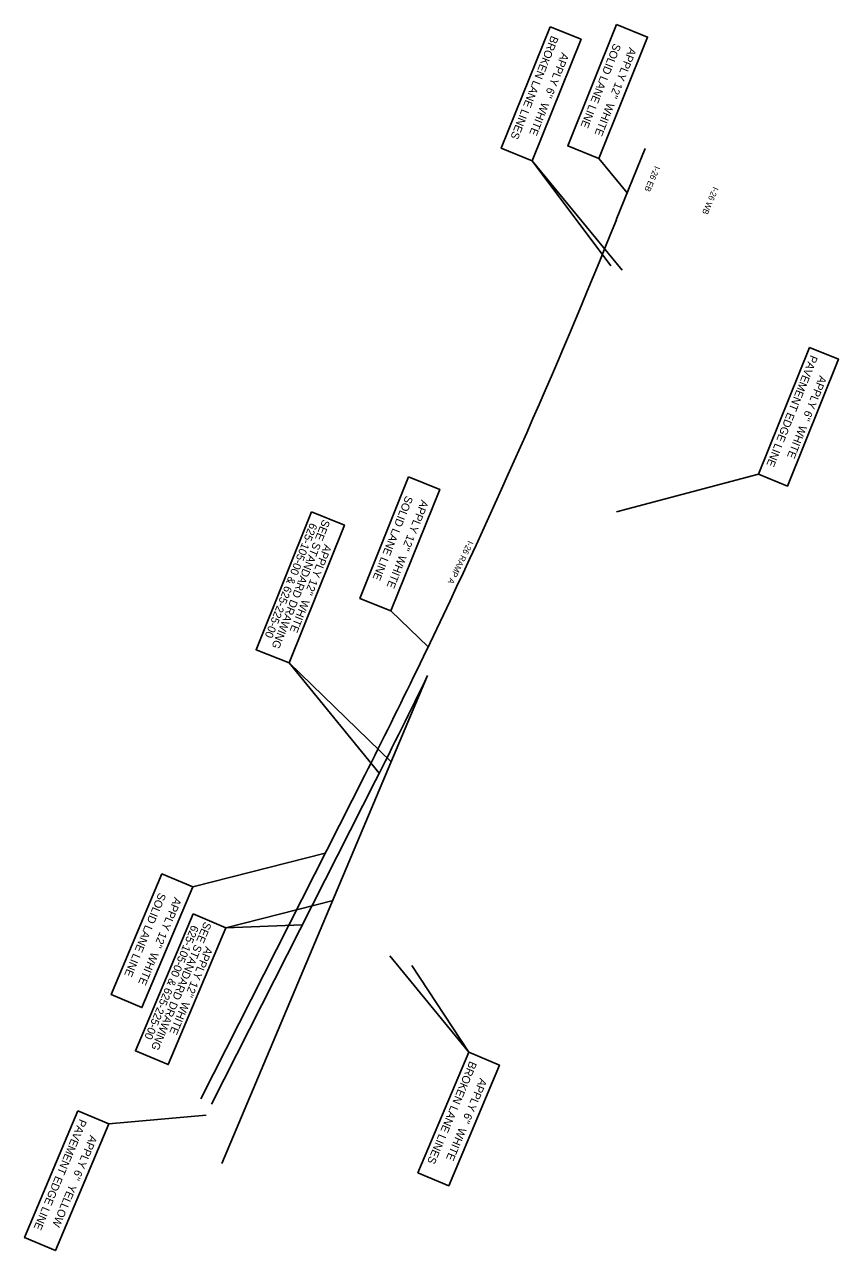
# Model space of a CAD drawing. Extents: x 1966013 to 1974896, y 789499 to 804826.
# Drawn here: x 1966799 to 1967612, y 793004 to 794229 of the extents above; entities that cross this region are included whole.
import ezdxf

# ---------------------------------------------------------------- set-up
doc = ezdxf.new("R2010")
doc.units = 0
for name, color, linetype in [('RD_EX_H2O_BlueLn', 7, 'Continuous'), ('RD_PD_Final_LnLine', 7, 'Continuous'), ('RD_PD_MedBWall', 7, 'Continuous')]:
    doc.layers.add(name, color=color, linetype=linetype)

msp = doc.modelspace()

# ---------------------------------------------------------------- linework, layer by layer
at = {"layer": 'RD_EX_H2O_BlueLn'}
for p, q in [((1967306.2, 794093.2), (1967396, 793983.7)), ((1967306.2, 794093.2), (1967384.8, 793988.1)), ((1967372.6, 794095.5), (1967401, 794060.9)), ((1967390.3, 793742.2), (1967532.4, 793779.7)), ((1967164.8, 793643.2), (1967202, 793607.2)), ((1967063, 793591.2), (1967153.2, 793481.1)), ((1967063, 793591.2), (1967165.2, 793492.3)), ((1966966.8, 793367.2), (1967099.1, 793401)), ((1966999.9, 793326.5), (1967107, 793353.8)), ((1966999.9, 793326.5), (1967076.2, 793329.5)), ((1967163.7, 793298.4), (1967242.6, 793202)), ((1967185.6, 793288.6), (1967242.6, 793202)), ((1966882.8, 793130.4), (1966980.1, 793139))]:
    msp.add_line(p, q, dxfattribs=at)
for points in [[(1967323.9, 794227.1), (1967275.2, 794105.7), (1967306.2, 794093.2), (1967355, 794214.6)], [(1967390.4, 794229.3), (1967341.6, 794107.9), (1967372.6, 794095.5), (1967421.4, 794216.8)], [(1967583.4, 793906.5), (1967532.4, 793779.7), (1967561.3, 793768), (1967612.3, 793894.9)], [(1967182.5, 793777.1), (1967133.8, 793655.7), (1967164.8, 793643.2), (1967213.6, 793764.6)], [(1967085.4, 793742.3), (1967030, 793604.4), (1967063, 793591.2), (1967118.4, 793729)], [(1966936, 793380.2), (1966885.2, 793259.6), (1966916, 793246.6), (1966966.8, 793367.2)], [(1966967.2, 793340.3), (1966909.4, 793203.4), (1966942.2, 793189.6), (1966999.9, 793326.5)], [(1967242.6, 793202), (1967191.8, 793081.5), (1967222.6, 793068.5), (1967273.4, 793189)], [(1966851.9, 793143.4), (1966798.6, 793016.8), (1966829.4, 793003.8), (1966882.8, 793130.4)]]:
    msp.add_lwpolyline(points, close=True, dxfattribs=at)
at = {"layer": 'RD_PD_Final_LnLine'}
for p, q in [((1967418.9, 794105.5), (1967390.2, 794034.1)), ((1967201.5, 793578.5), (1966995.9, 793090.9)), ((1966974.8, 793155.4), (1967138.7, 793479)), ((1966985.5, 793150), (1967149.4, 793473.6))]:
    msp.add_line(p, q, dxfattribs=at)
for radius, start, end in [(7012, 334.09201, 338.11901), (7012, 333.13743, 334.09253), (7024, 333.13743, 334.09253)]:
    msp.add_arc((1960883.4, 796647.4), radius, start, end, dxfattribs=at)

# ---------------------------------------------------------------- texts
at = {"layer": 'RD_EX_H2O_BlueLn'}
for s, rotation, p in [('BROKEN LANE LINES', 248.119, (1967325.2, 794218.7)), ('SOLID LANE LINE', 248.119, (1967387.7, 794211.1)), ("APPLY 12''  WHITE", 248.119, (1967403.2, 794206.9)), ("APPLY 6''  WHITE", 248.119, (1967335.7, 794201.8)), ('PAVEMENT EDGE LINE', 248.119, (1967584.4, 793899.5)), ("APPLY 6''  WHITE", 248.119, (1967593.4, 793879)), ('SOLID LANE LINE', 248.119, (1967179.8, 793758.9)), ("APPLY 12''  WHITE", 248.119, (1967195.4, 793754.7)), ('625-105-00 & 625-225-00', 248.119, (1967084.2, 793731.7)), ('SEE STANDARD DRAWING', 248.119, (1967096.8, 793735.2)), ("APPLY 12''  WHITE", 248.119, (1967098.5, 793710.4)), ('SOLID LANE LINE', 247.1375, (1966933, 793362.1)), ("APPLY 12''  WHITE", 247.1375, (1966948.5, 793357.5)), ('SEE STANDARD DRAWING', 247.1375, (1966978.4, 793333)), ('625-105-00 & 625-225-00', 247.1375, (1966965.8, 793329.7)), ("APPLY 12''  WHITE", 247.1375, (1966979.7, 793308.2)), ('BROKEN LANE LINES', 247.1375, (1967243.7, 793193.7)), ("APPLY 6''  WHITE", 247.1375, (1967253.9, 793176.6)), ('PAVEMENT EDGE LINE', 247.1375, (1966853.7, 793135.9)), ("APPLY 6''  YELLOW", 247.1375, (1966864.2, 793119.7))]:
    msp.add_text(s, height=8, rotation=rotation, dxfattribs=at).set_placement(p)
at = {"layer": 'RD_PD_MedBWall'}
for s, rotation, p in [('I-26 EB', 247.071, (1967428.6, 794088.4)), ('I-26 WB', 247.071, (1967487.1, 794067.6)), ('I-26 RAMP A', 243.7416, (1967242.2, 793713.9))]:
    msp.add_text(s, height=6, rotation=rotation, dxfattribs=at).set_placement(p)

doc.saveas('drawing.dxf')
